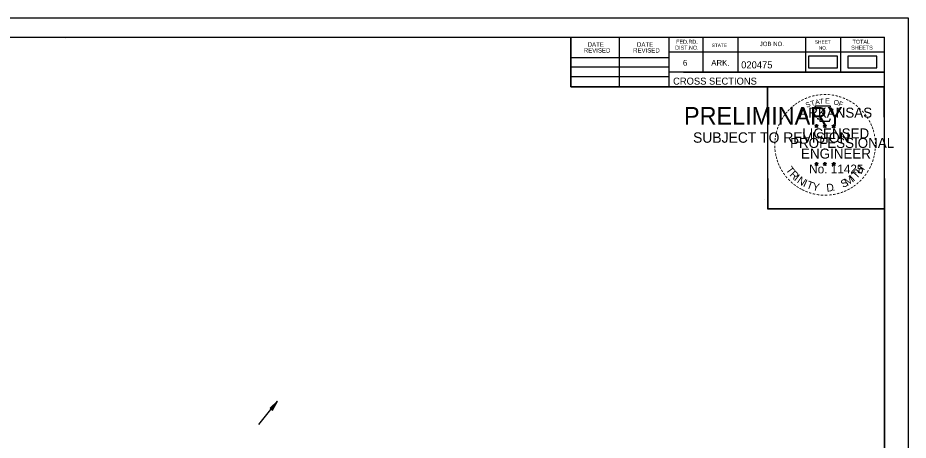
# Model space of a CAD drawing. Extents: x 1386544 to 1388153, y 379785 to 390999.
# Drawn here: x 1387917 to 1388094.9, y 381074.5 to 381158.8 of the extents above; entities that cross this region are included whole.
import ezdxf

# ---------------------------------------------------------------- set-up
doc = ezdxf.new("R2010")
doc.units = 0
for name, color, linetype in [('R_Border', 7, 'Continuous'), ('R_Border PE', 7, 'Continuous'), ('R_Border Prem', 7, 'Continuous'), ('R_No Plot', 7, 'Continuous'), ('R_Water', 7, 'Continuous'), ('S_SHOULDER', 7, 'Continuous')]:
    doc.layers.add(name, color=color, linetype=linetype)

msp = doc.modelspace()

# ---------------------------------------------------------------- linework, layer by layer
at = {"layer": 'R_Border'}
for p, q in [((1387773.97, 381154.92), (1388090.15, 381154.92)), ((1387926.49, 381154.66), (1387926.49, 381154.66)), ((1387926.49, 381154.66), (1387926.49, 381154.66)), ((1388027.51, 381145.04), (1388027.51, 381154.92)), ((1388037.19, 381145.04), (1388037.19, 381154.92)), ((1388047.05, 381154.92), (1388047.05, 381145.04)), ((1388053.89, 381154.92), (1388053.89, 381147.98)), ((1388060.83, 381154.92), (1388060.83, 381147.98)), ((1388074.41, 381154.92), (1388074.41, 381147.98)), ((1388081.35, 381154.92), (1388081.35, 381147.98)), ((1388090.15, 380949.46), (1388090.15, 381154.92)), ((1388090.15, 381151.98), (1388047.05, 381151.98)), ((1388090.15, 381152), (1388090.15, 381152)), ((1388027.51, 381150.9), (1388047.05, 381150.9)), ((1388027.51, 381149.04), (1388047.05, 381149.04)), ((1388090.15, 381147.98), (1388047.05, 381147.98)), ((1388050.01, 381147.98), (1388090.15, 381147.98)), ((1388027.51, 381147.1), (1388047.05, 381147.1)), ((1388090.15, 381145.04), (1388027.51, 381145.04))]:
    msp.add_line(p, q, dxfattribs=at)
at = {"layer": 'R_Border PE'}
for p, q in [((1388076.24, 381137.29), (1388076.59, 381137.18)), ((1388076.24, 381137.29), (1388076.49, 381137.25)), ((1388076.24, 381137.29), (1388076.47, 381137.17)), ((1388076.37, 381136.88), (1388076.59, 381137.18)), ((1388076.37, 381136.88), (1388076.5, 381137.13)), ((1388076.37, 381136.88), (1388076.58, 381137.1)), ((1388076.59, 381137.55), (1388076.54, 381137.29)), ((1388076.8, 381136.88), (1388076.58, 381137.1)), ((1388076.59, 381137.18), (1388076.59, 381137.55)), ((1388076.59, 381137.55), (1388076.63, 381137.3)), ((1388076.93, 381137.29), (1388076.59, 381137.18)), ((1388076.8, 381136.88), (1388076.59, 381137.18)), ((1388076.93, 381137.29), (1388076.65, 381137.24)), ((1388076.8, 381136.88), (1388076.66, 381137.17)), ((1388076.93, 381137.29), (1388076.73, 381137.19)), ((1388077.91, 381137.29), (1388078.26, 381137.18)), ((1388077.91, 381137.29), (1388078.16, 381137.25)), ((1388077.91, 381137.29), (1388078.14, 381137.17)), ((1388078.04, 381136.88), (1388078.26, 381137.18)), ((1388078.04, 381136.88), (1388078.17, 381137.13)), ((1388078.04, 381136.88), (1388078.25, 381137.1)), ((1388078.26, 381137.55), (1388078.21, 381137.29)), ((1388078.47, 381136.88), (1388078.25, 381137.1)), ((1388078.26, 381137.18), (1388078.26, 381137.55)), ((1388078.26, 381137.55), (1388078.3, 381137.3)), ((1388078.6, 381137.29), (1388078.26, 381137.18)), ((1388078.47, 381136.88), (1388078.26, 381137.18)), ((1388078.6, 381137.29), (1388078.32, 381137.24)), ((1388078.47, 381136.88), (1388078.33, 381137.17)), ((1388078.6, 381137.29), (1388078.4, 381137.19)), ((1388079.67, 381137.28), (1388080.02, 381137.17)), ((1388079.67, 381137.28), (1388079.92, 381137.23)), ((1388079.67, 381137.28), (1388079.91, 381137.16)), ((1388079.8, 381136.87), (1388080.02, 381137.17)), ((1388079.8, 381136.87), (1388079.93, 381137.12)), ((1388079.8, 381136.87), (1388080.02, 381137.09)), ((1388080.02, 381137.53), (1388079.98, 381137.28)), ((1388080.02, 381137.17), (1388080.02, 381137.53)), ((1388080.02, 381137.53), (1388080.07, 381137.28)), ((1388080.37, 381137.28), (1388080.02, 381137.17)), ((1388080.23, 381136.87), (1388080.02, 381137.17)), ((1388080.23, 381136.87), (1388080.02, 381137.09)), ((1388080.37, 381137.28), (1388080.08, 381137.23)), ((1388080.23, 381136.87), (1388080.1, 381137.16)), ((1388080.37, 381137.28), (1388080.16, 381137.18)), ((1388076.23, 381129.72), (1388076.58, 381129.61)), ((1388076.23, 381129.72), (1388076.49, 381129.67)), ((1388076.23, 381129.72), (1388076.47, 381129.6)), ((1388076.58, 381129.97), (1388076.54, 381129.72)), ((1388076.58, 381129.61), (1388076.58, 381129.97)), ((1388076.58, 381129.97), (1388076.63, 381129.72)), ((1388076.93, 381129.72), (1388076.58, 381129.61)), ((1388076.93, 381129.72), (1388076.64, 381129.67)), ((1388076.93, 381129.72), (1388076.72, 381129.62)), ((1388077.9, 381129.72), (1388078.25, 381129.61)), ((1388077.9, 381129.72), (1388078.15, 381129.67)), ((1388077.9, 381129.72), (1388078.14, 381129.6)), ((1388078.25, 381129.97), (1388078.21, 381129.72)), ((1388078.25, 381129.61), (1388078.25, 381129.97)), ((1388078.25, 381129.97), (1388078.3, 381129.72)), ((1388078.6, 381129.72), (1388078.25, 381129.61)), ((1388078.6, 381129.72), (1388078.31, 381129.67)), ((1388078.6, 381129.72), (1388078.39, 381129.62)), ((1388079.67, 381129.71), (1388080.02, 381129.6)), ((1388079.67, 381129.71), (1388079.92, 381129.66)), ((1388079.67, 381129.71), (1388079.91, 381129.59)), ((1388080.02, 381129.96), (1388079.98, 381129.71)), ((1388080.02, 381129.6), (1388080.02, 381129.96)), ((1388080.02, 381129.96), (1388080.07, 381129.71)), ((1388080.36, 381129.71), (1388080.02, 381129.6)), ((1388080.36, 381129.71), (1388080.08, 381129.66)), ((1388080.36, 381129.71), (1388080.16, 381129.61)), ((1388076.37, 381129.31), (1388076.58, 381129.61)), ((1388076.37, 381129.31), (1388076.49, 381129.55)), ((1388076.37, 381129.31), (1388076.58, 381129.53)), ((1388076.79, 381129.31), (1388076.58, 381129.61)), ((1388076.79, 381129.31), (1388076.58, 381129.52)), ((1388076.79, 381129.31), (1388076.66, 381129.6)), ((1388078.03, 381129.31), (1388078.25, 381129.61)), ((1388078.03, 381129.31), (1388078.16, 381129.55)), ((1388078.03, 381129.31), (1388078.25, 381129.53)), ((1388078.46, 381129.31), (1388078.25, 381129.61)), ((1388078.46, 381129.31), (1388078.25, 381129.52)), ((1388078.46, 381129.31), (1388078.33, 381129.6)), ((1388079.8, 381129.3), (1388080.02, 381129.6)), ((1388079.8, 381129.3), (1388079.93, 381129.54)), ((1388079.8, 381129.3), (1388080.02, 381129.52)), ((1388080.23, 381129.3), (1388080.02, 381129.6)), ((1388080.23, 381129.3), (1388080.02, 381129.51)), ((1388080.23, 381129.3), (1388080.09, 381129.59))]:
    msp.add_line(p, q, dxfattribs=at)
for points in [[(1388076.28, 381141.17), (1388076.55, 381140.34)], [(1388079.79, 381140.25), (1388079.93, 381140.53), (1388079.25, 381140.51), (1388079.39, 381141.17), (1388076.28, 381141.17)], [(1388076.77, 381138.75), (1388076.77, 381138.66), (1388077.33, 381138.64), (1388077.28, 381138.17), (1388079.15, 381138.17), (1388079.35, 381138.7)], [(1388076.59, 381137.55), (1388076.8, 381136.88), (1388076.24, 381137.29), (1388076.93, 381137.29), (1388076.37, 381136.88), (1388076.59, 381137.55)], [(1388078.26, 381137.55), (1388078.47, 381136.88), (1388077.91, 381137.29), (1388078.6, 381137.29), (1388078.04, 381136.88), (1388078.26, 381137.55)], [(1388080.02, 381137.53), (1388080.23, 381136.87), (1388079.67, 381137.28), (1388080.37, 381137.28), (1388079.8, 381136.87), (1388080.02, 381137.53)], [(1388076.58, 381129.97), (1388076.79, 381129.31), (1388076.23, 381129.72), (1388076.93, 381129.72), (1388076.37, 381129.31), (1388076.58, 381129.97)], [(1388078.25, 381129.97), (1388078.46, 381129.31), (1388077.9, 381129.72), (1388078.6, 381129.72), (1388078.03, 381129.31), (1388078.25, 381129.97)], [(1388080.02, 381129.96), (1388080.23, 381129.3), (1388079.67, 381129.71), (1388080.36, 381129.71), (1388079.8, 381129.3), (1388080.02, 381129.96)]]:
    msp.add_lwpolyline(points, dxfattribs=at)
for centre, radius in [((1388076.58, 381137.18), 0.172), ((1388076.58, 381137.18), 0.145), ((1388076.58, 381137.18), 0.116), ((1388076.58, 381137.18), 0.0991), ((1388076.58, 381137.18), 0.0747), ((1388076.58, 381137.18), 0.0495), ((1388076.58, 381137.18), 0.0296), ((1388078.25, 381137.18), 0.172), ((1388078.25, 381137.18), 0.145), ((1388078.25, 381137.18), 0.116), ((1388078.25, 381137.18), 0.0991), ((1388078.25, 381137.18), 0.0747), ((1388078.25, 381137.18), 0.0495), ((1388078.25, 381137.18), 0.0296), ((1388080.02, 381137.17), 0.172), ((1388080.02, 381137.17), 0.145), ((1388080.02, 381137.17), 0.116), ((1388080.02, 381137.17), 0.0991), ((1388080.02, 381137.17), 0.0747), ((1388080.02, 381137.17), 0.0495), ((1388080.02, 381137.17), 0.0296), ((1388076.58, 381129.61), 0.172), ((1388076.58, 381129.61), 0.145), ((1388076.58, 381129.61), 0.116), ((1388076.58, 381129.61), 0.0991), ((1388076.58, 381129.61), 0.0747), ((1388078.25, 381129.61), 0.172), ((1388078.25, 381129.61), 0.145), ((1388078.25, 381129.61), 0.116), ((1388078.25, 381129.61), 0.0991), ((1388078.25, 381129.61), 0.0747), ((1388080.02, 381129.6), 0.172), ((1388080.02, 381129.6), 0.145), ((1388080.02, 381129.6), 0.116), ((1388080.02, 381129.6), 0.0991), ((1388080.02, 381129.6), 0.0747), ((1388076.58, 381129.61), 0.0495), ((1388076.58, 381129.61), 0.0296), ((1388078.25, 381129.61), 0.0495), ((1388078.25, 381129.61), 0.0296), ((1388080.02, 381129.6), 0.0495), ((1388080.02, 381129.6), 0.0296)]:
    msp.add_circle(centre, radius, dxfattribs=at)
at = {"layer": 'R_No Plot'}
for p, q in [((1387761.57, 381158.81), (1388094.9, 381158.81)), ((1388066.19, 381122.58), (1388066.19, 381122.58))]:
    msp.add_line(p, q, dxfattribs=at)
for points in [[(1387761.56, 381158.81), (1388094.9, 381158.81), (1388094.9, 380945.47), (1387761.56, 380945.47)], [(1388007.89, 381154.92), (1388027.51, 381154.92), (1388027.51, 381145.04), (1388043.62, 381145.04), (1388066.82, 381145.04), (1388066.82, 381120.7), (1388090.15, 381120.7), (1388090.15, 380949.46), (1387773.97, 380949.46), (1387773.97, 381154.92)], [(1388066.82, 381145.04), (1388090.03, 381145.04), (1388090.15, 381120.7), (1388066.94, 381120.7)]]:
    msp.add_lwpolyline(points, close=True, dxfattribs=at)
at = {"layer": 'R_Water'}
for p, q in [((1387965.11, 381077.58), (1387968.89, 381082.24)), ((1387967.4, 381080.88), (1387968.89, 381082.24)), ((1387967.4, 381080.88), (1387968.89, 381082.24)), ((1387967.44, 381080.85), (1387968.68, 381081.98)), ((1387967.44, 381080.85), (1387968.68, 381081.98)), ((1387967.48, 381080.81), (1387968.47, 381081.71)), ((1387967.48, 381080.81), (1387968.47, 381081.71)), ((1387967.79, 381080.56), (1387968.47, 381081.71)), ((1387967.79, 381080.56), (1387968.47, 381081.71)), ((1387967.83, 381080.53), (1387968.68, 381081.98)), ((1387967.83, 381080.53), (1387968.68, 381081.98)), ((1387967.87, 381080.5), (1387968.89, 381082.24)), ((1387967.87, 381080.5), (1387968.89, 381082.24)), ((1387967.4, 381080.88), (1387967.87, 381080.5)), ((1387967.4, 381080.88), (1387967.87, 381080.5)), ((1387967.52, 381080.78), (1387968.26, 381081.46)), ((1387967.52, 381080.78), (1387968.26, 381081.46)), ((1387967.56, 381080.75), (1387968.04, 381081.19)), ((1387967.56, 381080.75), (1387968.04, 381081.19)), ((1387967.6, 381080.72), (1387967.83, 381080.93)), ((1387967.6, 381080.72), (1387967.83, 381080.93)), ((1387967.67, 381080.66), (1387967.83, 381080.93)), ((1387967.67, 381080.66), (1387967.83, 381080.93)), ((1387967.71, 381080.63), (1387968.04, 381081.19)), ((1387967.71, 381080.63), (1387968.04, 381081.19)), ((1387967.75, 381080.59), (1387968.26, 381081.46)), ((1387967.75, 381080.59), (1387968.26, 381081.46))]:
    msp.add_line(p, q, dxfattribs=at)
at = {"layer": 'S_SHOULDER'}
for points in [[(1388074.97, 381148.82), (1388080.8, 381148.82), (1388080.8, 381151.13), (1388074.97, 381151.13)], [(1388082.84, 381148.82), (1388088.67, 381148.82), (1388088.67, 381151.13), (1388082.84, 381151.13)]]:
    msp.add_lwpolyline(points, close=True, dxfattribs=at)

# ---------------------------------------------------------------- texts
at = {"layer": 'R_Border'}
for s, height, p in [('DATE', 0.879, (1388030.85, 381153.05)), ('DATE', 0.879, (1388040.71, 381153.05)), ('DIST.NO.', 0.782, (1388048.33, 381152.46)), ('FED.RD.', 0.782, (1388048.53, 381153.64)), ('STATE', 0.684, (1388055.65, 381152.96)), ('JOB NO.', 0.879, (1388065.23, 381153.16)), ('SHEET', 0.684, (1388076.27, 381153.64)), ('NO.', 0.684, (1388077.05, 381152.46)), ('SHEETS', 0.782, (1388083.51, 381152.46)), ('TOTAL', 0.782, (1388083.79, 381153.64)), ('REVISED', 0.879, (1388030.07, 381151.87)), ('REVISED', 0.879, (1388039.93, 381151.87)), ('6', 1.17, (1388049.89, 381149.24)), ('ARK.', 1.172, (1388055.55, 381149.24)), ('020475', 1.4, (1388061.53, 381148.72)), ('CROSS SECTIONS', 1.4, (1388047.92, 381145.47))]:
    msp.add_text(s, height=height, rotation=360, dxfattribs=at).set_placement(p)
at = {"layer": 'R_Border PE'}
for s, height, rotation, p in [('-', 1.6, 34.0636, (1388073.16, 381141.34)), ('-', 1.6, 28.7918, (1388073.76, 381141.71)), ('-', 1.6, 24.3072, (1388074.39, 381142.03)), ('-', 1.6, 19.1761, (1388075.03, 381142.3)), ('T', 1, 16.4036, (1388075.55, 381141.18)), ('-', 1.6, 13.6301, (1388075.78, 381142.54)), ('A', 1, 11.2132, (1388076.37, 381141.43)), ('-', 1.6, 10.2193, (1388076.45, 381142.7)), ('T', 1, 6.0228, (1388077.22, 381141.6)), ('-', 1.6, 5.8968, (1388077.18, 381142.81)), ('-', 1.6, 0.1862, (1388077.95, 381142.88)), ('E', 1, 0.8323, (1388078.33, 381141.71)), ('-', 1.6, 357.743, (1388078.68, 381142.87)), ('-', 1.6, 352.1617, (1388079.42, 381142.81)), ('O', 1, 350.4515, (1388079.93, 381141.5)), ('-', 1.6, 347.2049, (1388080.14, 381142.7)), ('F', 1, 340.0707, (1388080.88, 381141.27)), ('-', 1.6, 342.3362, (1388080.78, 381142.54)), ('-', 1.6, 337.8551, (1388081.51, 381142.32)), ('-', 1.6, 334.1211, (1388082.14, 381142.05)), ('-', 1.6, 329.6409, (1388082.72, 381141.77)), ('-', 1.6, 48.423, (1388071.23, 381139.67)), ('-', 1.6, 42.9622, (1388071.67, 381140.15)), ('-', 1.6, 38.9507, (1388072.11, 381140.57)), ('-', 1.6, 36.2317, (1388072.58, 381140.95)), ('ARKANSAS', 2, 360, (1388073.13, 381138.88)), ('S', 1, 21.594, (1388074.63, 381140.85)), ('-', 1.6, 325.8627, (1388083.36, 381141.41)), ('-', 1.6, 320.5297, (1388083.97, 381140.98)), ('-', 1.6, 315.5786, (1388084.57, 381140.49)), ('-', 1.6, 58.0706, (1388070.09, 381138.09)), ('-', 1.6, 54.2325, (1388070.41, 381138.62)), ('-', 1.6, 50.6142, (1388070.82, 381139.19)), ('-', 1.6, 309.8797, (1388085.14, 381139.94)), ('-', 1.6, 306.6522, (1388085.67, 381139.34)), ('-', 1.4, 303.6753, (1388086.15, 381138.77)), ('-', 1.6, 72.3945, (1388069.29, 381136.24)), ('-', 1.6, 67.7743, (1388069.51, 381136.87)), ('-', 1.6, 62.8713, (1388069.77, 381137.48)), ('DWB', 0.01, 360, (1388076.57, 381137.18)), ('DWB', 0.01, 360, (1388078.24, 381137.18)), ('DWB', 0.01, 360, (1388080.01, 381137.16)), ('-', 1.6, 299.6684, (1388086.47, 381138.16)), ('-', 1.6, 294.6628, (1388086.8, 381137.55)), ('-', 1.6, 290.5728, (1388087.05, 381136.98)), ('-', 1.6, 81.2013, (1388068.97, 381134.81)), ('-', 1.6, 75.461, (1388069.1, 381135.52)), ('LICENSED', 2, 360, (1388073.73, 381134.73)), ('-', 1.6, 285.1233, (1388087.29, 381136.4)), ('-', 1.6, 280.5493, (1388087.49, 381135.65)), ('-', 1.6, 94.1959, (1388068.9, 381132.69)), ('-', 1.6, 89.0622, (1388068.86, 381133.42)), ('-', 1.6, 85.1863, (1388068.89, 381134.12)), ('PROFESSIONAL', 2, 360, (1388071.3, 381132.83)), ('-', 1.6, 276.5962, (1388087.65, 381134.89)), ('-', 1.6, 274.3301, (1388087.71, 381134.16)), ('-', 1.6, 269.9407, (1388087.74, 381133.53)), ('-', 1.6, 98.9479, (1388068.97, 381132.03)), ('-', 1.6, 101.7149, (1388069.11, 381131.29)), ('ENGINEER', 2, 360, (1388073.49, 381130.7)), ('-', 1.6, 260.9953, (1388087.65, 381132.21)), ('-', 1.6, 263.5172, (1388087.72, 381132.87)), ('-', 1.6, 105.4578, (1388069.27, 381130.7)), ('-', 1.6, 109.0874, (1388069.48, 381130.07)), ('-', 1.6, 114.0643, (1388069.74, 381129.47)), ('-', 1.6, 247.8887, (1388087.14, 381130.14)), ('-', 1.6, 252.8681, (1388087.36, 381130.81)), ('-', 1.6, 255.7626, (1388087.54, 381131.53)), ('-', 1.6, 115.7289, (1388070.04, 381128.85)), ('-', 1.6, 120.4471, (1388070.4, 381128.27)), ('-', 1.6, 125.8934, (1388070.8, 381127.71)), ('T', 1.54, 306.0406, (1388070.34, 381128.45)), ('R', 1.54, 314.005, (1388071.1, 381127.4)), ('No. 11425', 1.757, 360, (1388075.12, 381127.75)), ('DWB', 0.01, 360, (1388076.57, 381129.6)), ('DWB', 0.01, 360, (1388078.24, 381129.6)), ('DWB', 0.01, 360, (1388080, 381129.59)), ('T', 1.54, 46.6444, (1388084.57, 381126.54)), ('H', 1.54, 54.6088, (1388085.46, 381127.48)), ('-', 1.6, 239.0712, (1388086.48, 381128.76)), ('-', 1.6, 244.6197, (1388086.88, 381129.51)), ('-', 1.6, 130.7181, (1388071.26, 381127.15)), ('-', 1.6, 134.2238, (1388071.78, 381126.61)), ('-', 1.6, 138.9338, (1388072.31, 381126.15)), ('I', 1.54, 321.9694, (1388072, 381126.47)), ('N', 1.54, 326.5002, (1388072.57, 381125.99)), ('I', 1.54, 335.3603, (1388073.78, 381125.21)), ('T', 1.54, 339.8912, (1388074.44, 381124.88)), ('S', 1.54, 26.9312, (1388081.89, 381124.81)), ('M', 1.54, 32.6563, (1388082.73, 381125.21)), ('I', 1.54, 42.1136, (1388084.01, 381126.06)), ('-', 1.6, 225.7653, (1388085.17, 381126.98)), ('-', 1.6, 231.2538, (1388085.65, 381127.54)), ('-', 1.6, 233.8452, (1388086.08, 381128.11)), ('-', 1.6, 144.6463, (1388072.86, 381125.74)), ('-', 1.6, 148.0898, (1388073.42, 381125.37)), ('-', 1.6, 151.5704, (1388074, 381125.04)), ('-', 1.6, 154.6002, (1388074.52, 381124.8)), ('Y', 1.54, 347.8556, (1388075.66, 381124.44)), ('D', 1.54, 6.3969, (1388078.64, 381124.08)), ('.', 1.54, 13.7642, (1388079.83, 381124.2)), ('-', 1.6, 204.2516, (1388082.38, 381124.94)), ('-', 1.6, 207.3568, (1388083.01, 381125.26)), ('-', 1.6, 212.2491, (1388083.57, 381125.61)), ('-', 1.6, 215.7363, (1388084.1, 381126)), ('-', 1.6, 221.0851, (1388084.65, 381126.47)), ('-', 1.6, 158.5612, (1388075.15, 381124.54)), ('-', 1.6, 162.7983, (1388075.84, 381124.33)), ('-', 1.6, 167.5555, (1388076.55, 381124.17)), ('-', 1.6, 173.1155, (1388077.32, 381124.06)), ('-', 1.6, 176.5183, (1388078.07, 381124)), ('-', 1.6, 181.5918, (1388078.81, 381124.02)), ('-', 1.6, 185.8167, (1388079.62, 381124.1)), ('-', 1.6, 191.2858, (1388080.36, 381124.23)), ('-', 1.6, 195.4743, (1388081.09, 381124.43)), ('-', 1.6, 200.7184, (1388081.77, 381124.67))]:
    msp.add_text(s, height=height, rotation=rotation, dxfattribs=at).set_placement(p)
at = {"layer": 'R_Border Prem'}
for s, height, p in [('PRELIMINARY', 3.5, (1388050.1, 381137.5)), ('DWB', 0.01, (1388050.85, 381139.35)), ('SUBJECT TO REVISION', 2.0751, (1388051.91, 381133.87))]:
    msp.add_text(s, height=height, rotation=360, dxfattribs=at).set_placement(p)

doc.saveas('drawing.dxf')
